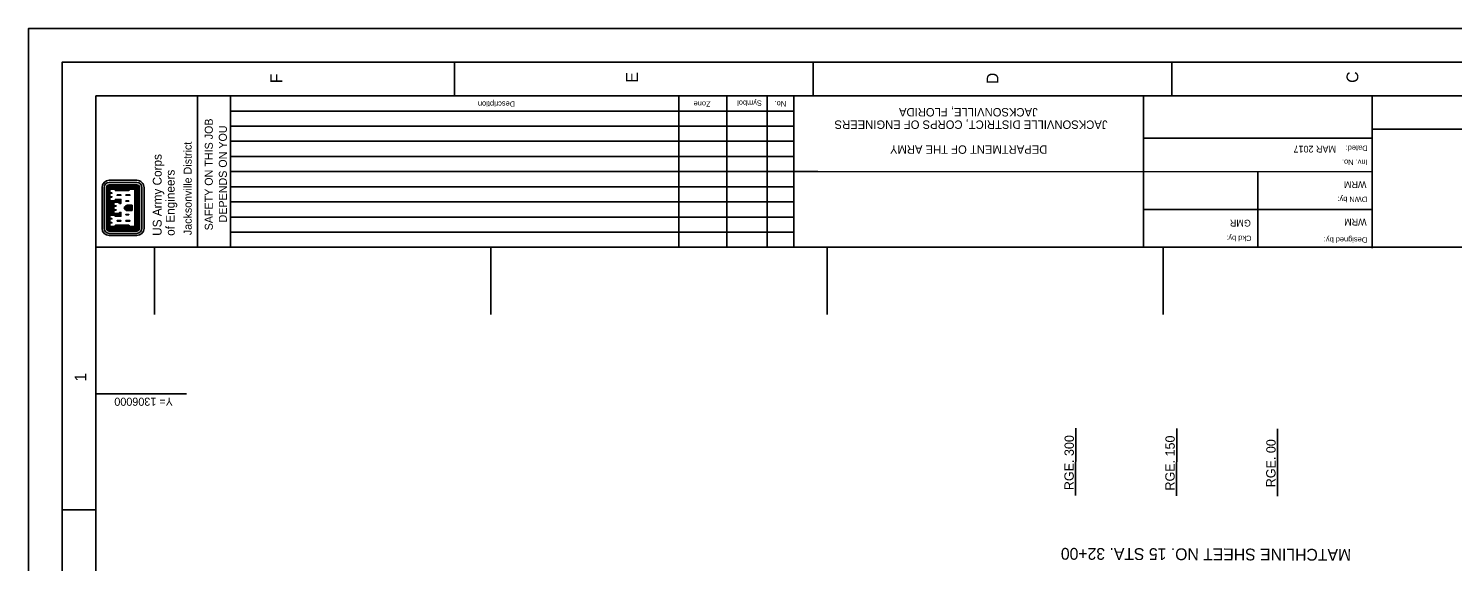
# Model space of a CAD drawing. Extents: x 516313 to 519713, y 1302143 to 1306543.
# Drawn here: x 516313 to 518430, y 1305751 to 1306543 of the extents above; entities that cross this region are included whole.
import ezdxf

# ---------------------------------------------------------------- set-up
doc = ezdxf.new("R2010")
doc.units = 0
for name, color, linetype in [('G-ANNO-NPLT', 7, 'Continuous'), ('G-ANNO-TEXT-DRWG', 7, 'Continuous'), ('G-ANNO-TEXT-LOGO', 7, 'Continuous'), ('G-ANNO-TEXT-PROJ', 7, 'Continuous'), ('G-ANNO-TEXT-TTLB', 7, 'Continuous'), ('G-ANNO-TTLB', 7, 'Continuous'), ('V-ALGN-TEXT', 7, 'Continuous'), ('V-ANNO-MATC-IDEN', 7, 'Continuous'), ('V-TOPO-COOR-STAT', 7, 'Continuous')]:
    doc.layers.add(name, color=color, linetype=linetype)

msp = doc.modelspace()

# ---------------------------------------------------------------- linework, layer by layer
at = {"layer": 'G-ANNO-NPLT'}
msp.add_lwpolyline([(516312.5, 1302142.9), (516312.5, 1306542.8), (519712.5, 1306542.8), (519712.5, 1302142.9)], close=True, dxfattribs=at)
msp.add_lwpolyline([(516362.5, 1306542.8), (516312.5, 1306542.8), (516312.5, 1306492.8)], dxfattribs=at)
at = {"layer": 'G-ANNO-TEXT-LOGO'}
for p, q in [((516473.6, 1306317.4), (516432.6, 1306317.4)), ((516432.6, 1306314.1), (516473.6, 1306314.1)), ((516421.9, 1306306.7), (516421.9, 1306245.9)), ((516425.1, 1306245.9), (516425.1, 1306306.7)), ((516428.5, 1306306.7), (516428.5, 1306245.9)), ((516429.4, 1306306.7), (516429.4, 1306245.9)), ((516430.3, 1306306.7), (516430.3, 1306245.9)), ((516431.1, 1306306.7), (516431.1, 1306245.9)), ((516432, 1306306.7), (516432, 1306245.9)), ((516432.6, 1306310.7), (516473.6, 1306310.7)), ((516432.6, 1306309.8), (516473.6, 1306309.8)), ((516432.6, 1306308.9), (516473.6, 1306308.9)), ((516432.6, 1306308.1), (516473.6, 1306308.1)), ((516432.6, 1306307.2), (516473.6, 1306307.2)), ((516432.6, 1306306.3), (516473.3, 1306306.3)), ((516432.6, 1306305.5), (516472.4, 1306305.5)), ((516441.4, 1306304.8), (516462.2, 1306304.8)), ((516442.2, 1306303.9), (516461.3, 1306303.9)), ((516472.4, 1306305.5), (516472.4, 1306247.1)), ((516473.3, 1306306.3), (516473.3, 1306246.3)), ((516474.2, 1306306.7), (516474.2, 1306245.9)), ((516475, 1306306.7), (516475, 1306245.9)), ((516475.9, 1306306.7), (516475.9, 1306245.9)), ((516476.8, 1306306.7), (516476.8, 1306245.9)), ((516477.6, 1306306.7), (516477.6, 1306245.9)), ((516481.1, 1306306.7), (516481.1, 1306245.9)), ((516484.4, 1306245.9), (516484.4, 1306306.7)), ((516432.8, 1306267), (516432.8, 1306285.6)), ((516433.7, 1306267), (516433.7, 1306285.6)), ((516434.5, 1306267), (516434.5, 1306285.6)), ((516435.4, 1306267), (516435.4, 1306285.6)), ((516436.3, 1306267), (516436.3, 1306285.6)), ((516437.1, 1306267), (516437.1, 1306285.6)), ((516438, 1306267), (516438, 1306285.6)), ((516466.5, 1306280.3), (516459.8, 1306280.3)), ((516466.5, 1306279.5), (516459.8, 1306279.5)), ((516466.5, 1306278.6), (516459.8, 1306278.6)), ((516466.5, 1306277.7), (516459.8, 1306277.7)), ((516466.5, 1306276.9), (516459.8, 1306276.9)), ((516466.5, 1306275.7), (516459.8, 1306275.7)), ((516466.5, 1306274.9), (516459.8, 1306274.9)), ((516466.5, 1306274), (516459.8, 1306274)), ((516466.5, 1306273.1), (516459.8, 1306273.1)), ((516466.5, 1306272.3), (516459.8, 1306272.3)), ((516466.5, 1306272.3), (516466.5, 1306280.3)), ((516442.2, 1306248.7), (516461.3, 1306248.7)), ((516432.6, 1306247.1), (516472.4, 1306247.1)), ((516432.6, 1306246.3), (516473.3, 1306246.3)), ((516432.6, 1306245.4), (516473.6, 1306245.4)), ((516432.6, 1306244.5), (516473.6, 1306244.5)), ((516432.6, 1306243.6), (516473.6, 1306243.6)), ((516432.6, 1306242.8), (516473.6, 1306242.8)), ((516432.6, 1306241.9), (516473.6, 1306241.9)), ((516473.6, 1306238.4), (516432.6, 1306238.4)), ((516432.6, 1306235.2), (516473.6, 1306235.2)), ((516441.3, 1306247.8), (516462.3, 1306247.8))]:
    msp.add_line(p, q, dxfattribs=at)
for points in [[(516432.6, 1306247.8), (516440.5, 1306247.8), (516442.2, 1306249.5), (516461.3, 1306249.5), (516463.1, 1306247.8), (516471.8, 1306247.8), (516471.8, 1306304.8), (516463.1, 1306304.8), (516461.3, 1306303), (516442.2, 1306303), (516440.5, 1306304.8), (516432.6, 1306304.8), (516432.6, 1306297.3), (516432.6, 1306291.5), (516432.6, 1306286.1), (516440.5, 1306286.1), (516442.2, 1306288), (516449.2, 1306288), (516449.2, 1306283.8), (516448.5, 1306283.8), (516446.7, 1306285.6), (516438.9, 1306285.6), (516438.9, 1306278.1), (516438.9, 1306272.3), (516438.9, 1306267), (516446.7, 1306267), (516448.5, 1306268.8), (516449.2, 1306268.8), (516449.2, 1306264.6), (516442.2, 1306264.6), (516440.5, 1306266.4), (516432.6, 1306266.4), (516432.6, 1306258.9), (516432.6, 1306253.1), (516432.6, 1306247.8)], [(516433.5, 1306248.6), (516440.1, 1306248.6), (516441.9, 1306250.4), (516461.7, 1306250.4), (516463.5, 1306248.6), (516470.9, 1306248.6), (516470.9, 1306304), (516463.5, 1306304), (516461.7, 1306302.1), (516441.9, 1306302.1), (516440.1, 1306304), (516433.5, 1306304), (516433.5, 1306298.6), (516436.6, 1306298.6), (516436.6, 1306298.1), (516433.5, 1306298.1), (516433.5, 1306292.8), (516436.6, 1306292.8), (516436.6, 1306292.4), (516433.5, 1306292.4), (516433.5, 1306287), (516440.1, 1306287), (516441.9, 1306288.8), (516450, 1306288.8), (516450, 1306283), (516448.1, 1306283), (516446.3, 1306284.8), (516439.7, 1306284.8), (516439.7, 1306279.4), (516442.8, 1306279.4), (516442.8, 1306279), (516439.7, 1306279), (516439.7, 1306273.6), (516442.8, 1306273.6), (516442.8, 1306273.1), (516439.7, 1306273.1), (516439.7, 1306267.8), (516446.3, 1306267.8), (516448.1, 1306269.6), (516450, 1306269.6), (516450, 1306263.8), (516441.9, 1306263.8), (516440.1, 1306265.6), (516433.5, 1306265.6), (516433.5, 1306260.3), (516436.6, 1306260.3), (516436.6, 1306259.8), (516433.5, 1306259.8), (516433.5, 1306254.4), (516436.6, 1306254.4), (516436.6, 1306254), (516433.5, 1306254), (516433.5, 1306248.6)], [(516444.2, 1306295.7), (516450, 1306295.7), (516450, 1306295.2), (516444.2, 1306295.2), (516444.2, 1306295.7)], [(516457.5, 1306295.7), (516463.4, 1306295.7), (516463.4, 1306295.2), (516457.5, 1306295.2), (516457.5, 1306295.7)], [(516442.1, 1306286.6), (516442.6, 1306287.1), (516448.3, 1306287.1), (516448.3, 1306285.3), (516447, 1306286.5), (516442, 1306286.5)], [(516457.5, 1306286.6), (516461.6, 1306286.6), (516461.6, 1306286.1), (516457.5, 1306286.1), (516457.5, 1306286.6)], [(516442.1, 1306266), (516442.6, 1306265.5), (516448.3, 1306265.5), (516448.3, 1306267.4), (516447, 1306266.1), (516442, 1306266.1)], [(516444.2, 1306256.8), (516450, 1306256.8), (516450, 1306257.4), (516444.2, 1306257.4), (516444.2, 1306256.8)], [(516457.5, 1306266), (516461.6, 1306266), (516461.6, 1306266.5), (516457.5, 1306266.5), (516457.5, 1306266)], [(516457.5, 1306256.8), (516463.4, 1306256.8), (516463.4, 1306257.4), (516457.5, 1306257.4), (516457.5, 1306256.8)]]:
    msp.add_lwpolyline(points, dxfattribs=at)
for centre, major_axis, start_param, end_param in [((516432.6, 1306306.6), (0, 10.7), 6.283169, 7.853965), ((516432.6, 1306306.6), (0, 7.49), 6.28317, 7.853966), ((516473.7, 1306306.6), (0, 10.7), 4.712373, 6.28317), ((516473.7, 1306306.6), (0, -7.49), 1.570781, 3.141577), ((516432.6, 1306306.6), (0, 4.02), 6.283169, 7.853965), ((516432.6, 1306306.6), (0, 3.15), 6.283169, 7.853965), ((516432.6, 1306306.6), (0, 2.28), 6.283169, 7.853965), ((516432.6, 1306306.6), (0, 1.41), 6.283169, 7.853965), ((516432.6, 1306306.6), (0, 0.546), 6.283169, 7.853965), ((516473.7, 1306306.6), (0, 4.02), 4.712373, 6.28317), ((516473.7, 1306306.6), (0, 3.15), 4.712373, 6.28317), ((516473.7, 1306306.6), (0, 2.28), 4.712373, 6.28317), ((516473.7, 1306306.6), (0, 1.41), 4.712373, 6.28317), ((516473.7, 1306306.6), (0, 0.546), 4.712373, 6.28317), ((516460.3, 1306274.8), (0, 5.55), 0.068795, 1.29842), ((516460.3, 1306277.8), (0, -5.55), 4.985832, 6.214359), ((516460.3, 1306274.8), (0, 4.69), 0.068795, 1.335689), ((516460.3, 1306277.8), (0, -4.69), 4.947465, 6.21436), ((516460.3, 1306274.8), (0, 3.82), 0.068795, 1.335689), ((516460.3, 1306277.8), (0, -3.82), 4.947465, 6.21436), ((516460.3, 1306274.8), (0, 2.95), 0.068794, 1.335689), ((516460.3, 1306277.8), (0, -2.95), 4.947465, 6.21436), ((516460.3, 1306277.8), (0, -2.08), 4.947465, 6.214359), ((516460.3, 1306274.8), (0, 2.08), 0.068794, 1.335689), ((516432.6, 1306245.9), (0, 10.7), 1.57078, 3.141576), ((516432.6, 1306245.9), (0, 7.49), 1.57078, 3.141576), ((516432.6, 1306245.9), (0, 4.02), 1.57078, 3.141576), ((516432.6, 1306245.9), (0, 3.15), 1.57078, 3.141576), ((516432.6, 1306245.9), (0, 2.28), 1.57078, 3.141576), ((516432.6, 1306245.9), (0, 1.41), 1.57078, 3.141576), ((516432.6, 1306245.9), (0, 0.546), 1.57078, 3.141576), ((516473.7, 1306245.9), (0, -4.02), 6.28317, 7.853966), ((516473.7, 1306245.9), (0, -3.15), 6.28317, 7.853966), ((516473.7, 1306245.9), (0, -2.28), 6.28317, 7.853966), ((516473.7, 1306245.9), (0, -1.41), 6.28317, 7.853966), ((516473.7, 1306245.9), (0, -0.546), 6.28317, 7.853966), ((516473.7, 1306245.9), (0, -10.7), 6.28317, 7.853966), ((516473.7, 1306245.9), (0, -7.49), 6.28317, 7.853966)]:
    msp.add_ellipse(centre, major_axis=major_axis, ratio=0.99964, start_param=start_param, end_param=end_param, dxfattribs=at)
at = {"layer": 'G-ANNO-TTLB'}
for p, q in [((516946, 1306492.8), (516946, 1306442.8)), ((517479.3, 1306492.8), (517479.3, 1306442.8)), ((518012.6, 1306492.8), (518012.6, 1306442.8)), ((516563.8, 1306217.8), (516563.8, 1306442.8)), ((516612.9, 1306217.2), (516612.9, 1306442.2)), ((517279.8, 1306217.8), (517279.8, 1306442.8)), ((517351, 1306217.8), (517351, 1306442.8)), ((517411, 1306217.8), (517411, 1306442.8)), ((517450.8, 1306217.8), (517450.8, 1306442.8)), ((517970.7, 1306217), (517970.7, 1306442.8)), ((518310.4, 1306216.6), (518310.4, 1306442.8)), ((516612.9, 1306420.2), (517450.8, 1306420.2)), ((516612.9, 1306397.7), (517450.8, 1306397.7)), ((517970.7, 1306379.9), (518310.4, 1306379.9)), ((518310.4, 1306393.5), (518661.8, 1306393.5)), ((516612.9, 1306375.2), (517450.8, 1306375.2)), ((516612.9, 1306352.7), (517450.8, 1306352.7)), ((516612.9, 1306330.2), (517450.8, 1306330.2)), ((518310.4, 1306329.7), (517450.8, 1306330.3)), ((517450.8, 1306330.3), (517486.2, 1306330.3)), ((518140.6, 1306217), (518140.6, 1306329.8)), ((516612.9, 1306307.7), (517450.8, 1306307.7)), ((516612.9, 1306285.2), (517450.8, 1306285.2)), ((518310.3, 1306273.7), (517970.7, 1306274)), ((516612.9, 1306262.7), (517450.8, 1306262.7)), ((516612.9, 1306240.2), (517450.8, 1306240.2)), ((516412.5, 1306217.8), (519612.5, 1306217.8)), ((516362.5, 1305827.9), (516412.5, 1305827.9))]:
    msp.add_line(p, q, dxfattribs=at)
for points in [[(519662.5, 1302192.9), (519662.5, 1306492.8), (516362.5, 1306492.8), (516362.5, 1302192.9)], [(516412.5, 1306442.8), (516412.5, 1302317.9), (519612.5, 1302317.9), (519612.5, 1306442.8)]]:
    msp.add_lwpolyline(points, close=True, dxfattribs=at)
at = {"layer": 'V-ALGN-TEXT'}
for p, q in [((517869.6, 1305849.1), (517870, 1305949.1)), ((518019.6, 1305848.6), (518020, 1305948.6)), ((518169.6, 1305848), (518170, 1305948))]:
    msp.add_line(p, q, dxfattribs=at)
at = {"layer": 'V-TOPO-COOR-STAT'}
for p, q in [((516500, 1306117.8), (516500, 1306217.8)), ((517000, 1306117.8), (517000, 1306217.8)), ((517500, 1306117.8), (517500, 1306217.8)), ((518000, 1306117.8), (518000, 1306217.8)), ((516547.5, 1306000), (516412.5, 1306000))]:
    msp.add_line(p, q, dxfattribs=at)

# ---------------------------------------------------------------- texts
at = {"layer": 'G-ANNO-TEXT-DRWG'}
for s, p in [('WRM', (518302.1, 1306315.7)), ('GMR', (518130.2, 1306258.6)), ('WRM', (518302.3, 1306260.1))]:
    msp.add_text(s, height=10, rotation=180, dxfattribs=at).set_placement(p)
at = {"layer": 'G-ANNO-TEXT-PROJ'}
msp.add_text('MAR 2017', height=10, rotation=180, dxfattribs=at).set_placement((518256.8, 1306368.6))
at = {"layer": 'G-ANNO-TEXT-TTLB'}
for s, height, rotation, p in [('Description', 8, 180, (517036.1, 1306434.5)), ('Zone', 8, 180, (517326.8, 1306434.8)), ('Symbol', 8, 180, (517403.1, 1306435.9)), ('No.', 8, 180, (517439.2, 1306434.9)), ('JACKSONVILLE, FLORIDA', 12.5, 180, (517813.2, 1306424.7)), ('SAFETY ON THIS JOB', 11.9, 90, (516586.6, 1306242.9)), ('DEPENDS ON YOU', 11.9, 90, (516607.5, 1306254.7)), ('JACKSONVILLE DISTRICT, CORPS OF ENGINEERS', 12.5, 180, (517917, 1306406.2)), ('US Army Corps', 13.086, 90, (516510.5, 1306234.8)), ('Jacksonville District', 11.9, 90, (516555.2, 1306235.8)), ('DEPARTMENT OF THE ARMY', 12.5, 180, (517827.6, 1306369.2)), ('Dated:', 8, 180, (518303.7, 1306368.9)), ('Inv. No.', 8, 180, (518303.8, 1306348.1)), ('of Engineers', 13.086, 90, (516529.9, 1306234.8)), ('DWN by:', 8, 180, (518303.1, 1306292.9)), ('Ckd by:', 8, 180, (518131.1, 1306235.1)), ('Designed by:', 8, 180, (518303.1, 1306232.7))]:
    msp.add_text(s, height=height, rotation=rotation, dxfattribs=at).set_placement(p)
at = {"layer": 'G-ANNO-TTLB'}
for s, p in [('F', (516689.9, 1306461.6)), ('E', (517218.7, 1306462.4)), ('D', (517754.8, 1306460.2)), ('C', (518290, 1306462.1)), ('1', (516398.7, 1306018.3))]:
    msp.add_text(s, height=17.5, rotation=90, dxfattribs=at).set_placement(p)
at = {"layer": 'V-ALGN-TEXT'}
for s, p in [('RGE. 300', (517866.8, 1305856.9)), ('RGE. 150', (518016.8, 1305856.3)), ('RGE. 00', (518166.8, 1305861.2))]:
    msp.add_text(s, height=13.92, rotation=89.7829, dxfattribs=at).set_placement(p)
at = {"layer": 'V-ANNO-MATC-IDEN'}
msp.add_text('MATCHLINE SHEET NO. 15 STA. 32+00', height=17.52, rotation=179.7829, dxfattribs=at).set_placement((518279.3, 1305769.5))
at = {"layer": 'V-TOPO-COOR-STAT'}
msp.add_text('Y= 1306000', height=12, rotation=180, dxfattribs=at).set_placement((516527.2, 1305994.3))

doc.saveas('drawing.dxf')
